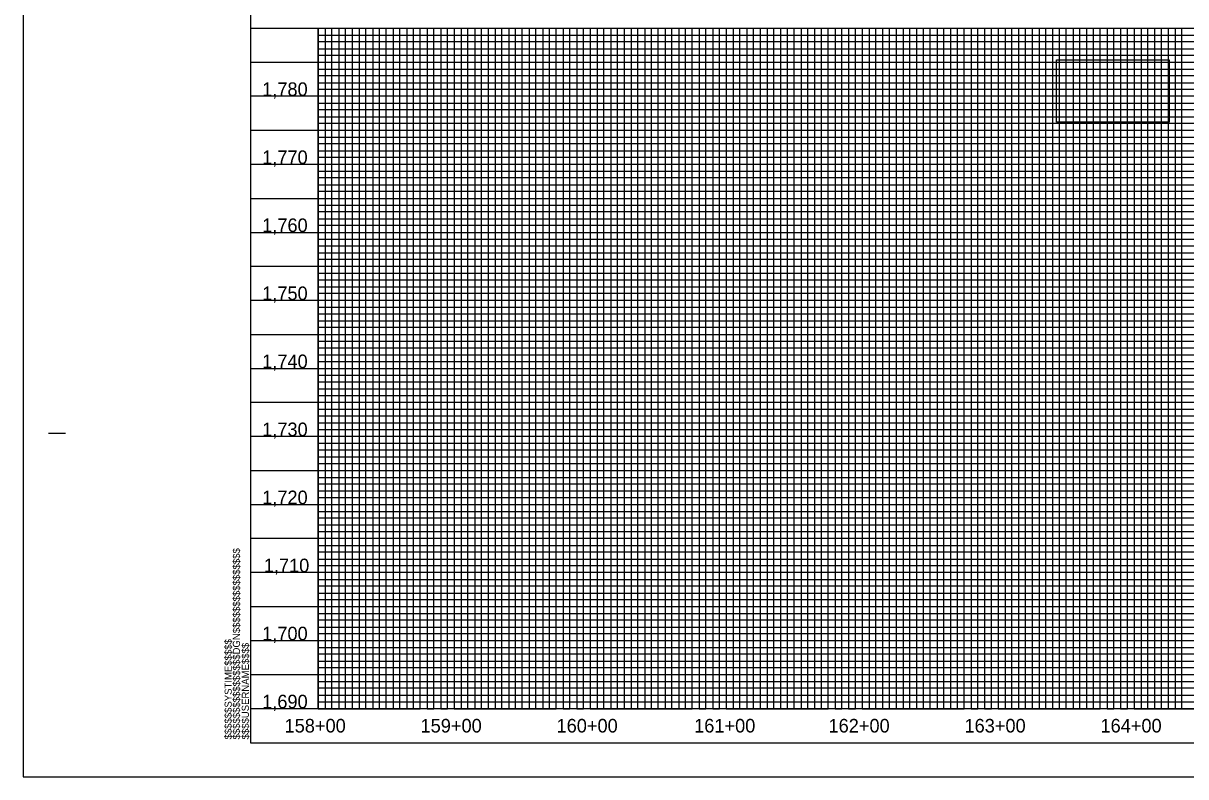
# Model space of a CAD drawing. Extents: x 505602 to 507286, y 483109 to 484209.
# Drawn here: x 505602 to 506457, y 483109 to 483662 of the extents above; entities that cross this region are included whole.
import ezdxf

# ---------------------------------------------------------------- set-up
doc = ezdxf.new("R2010")
doc.units = 0
for name, color, linetype in [('Exist Vertical Profile Vertical Axis Label', 7, 'Continuous'), ('Prop Grid Mask', 7, 'Continuous'), ('Sheet Layout Profile Border Port 2', 7, 'Continuous'), ('Sheet Plot Border Outside CELL', 7, 'Continuous'), ('Sheet Profile CELL', 7, 'Continuous'), ('Sheet Profile Grid Major CELL', 7, 'Continuous'), ('Sheet Profile Grid Middle CELL', 7, 'Continuous'), ('Sheet Profile Grid Minor CELL', 7, 'Continuous')]:
    doc.layers.add(name, color=color, linetype=linetype)

msp = doc.modelspace()

# ---------------------------------------------------------------- linework, layer by layer
at = {"layer": 'Prop Grid Mask'}
msp.add_lwpolyline([(506362.01, 483635.44), (506444.87, 483635.44), (506444.87, 483589.8), (506362.01, 483589.8)], close=True, dxfattribs=at)
at = {"layer": 'Sheet Layout Profile Border Port 2'}
msp.add_lwpolyline([(505819.08, 483658.71), (507219.08, 483658.71), (507219.08, 483158.71), (505819.08, 483158.71)], close=True, dxfattribs=at)
at = {"layer": 'Sheet Plot Border Outside CELL'}
msp.add_lwpolyline([(505602.08, 483108.71), (507286.08, 483108.71), (507286.08, 484208.71), (505602.08, 484208.71)], close=True, dxfattribs=at)
at = {"layer": 'Sheet Profile CELL'}
for p, q in [((505769.08, 483658.71), (507269.08, 483658.71)), ((505620.58, 483361.21), (505633.08, 483361.21)), ((507269.08, 483158.71), (505769.08, 483158.71)), ((505769.08, 483133.71), (507269.08, 483133.71)), ((505769.08, 483133.71), (505769.08, 483133.71)), ((505769.08, 483133.71), (505769.08, 483133.71)), ((505769.08, 483133.71), (505769.08, 483133.71)), ((505769.08, 483133.71), (505769.08, 483133.71)), ((505769.08, 483133.71), (505769.08, 483133.71)), ((505769.08, 483133.71), (505769.08, 483133.71)), ((505769.08, 483133.71), (505769.08, 483133.71))]:
    msp.add_line(p, q, dxfattribs=at)
msp.add_lwpolyline([(507269.08, 484183.71), (505769.08, 484183.71), (505769.08, 483133.71), (507269.08, 483133.71)], close=True, dxfattribs=at)
msp.add_lwpolyline([(505806.58, 483133.71), (505806.58, 483133.71)], dxfattribs=at)
at = {"layer": 'Sheet Profile Grid Major CELL'}
for p, q in [((506269.08, 483658.71), (506319.08, 483658.71)), ((506369.08, 483658.71), (506419.08, 483658.71))]:
    msp.add_line(p, q, dxfattribs=at)
for points in [[(505819.08, 483658.71), (505819.08, 483158.71), (505869.08, 483158.71), (505869.08, 483658.71), (505919.08, 483658.71), (505919.08, 483158.71), (505969.08, 483158.71), (505969.08, 483658.71), (506019.08, 483658.71), (506019.08, 483158.71), (506069.08, 483158.71), (506069.08, 483658.71), (506119.08, 483658.71), (506119.08, 483158.71), (506169.08, 483158.71), (506169.08, 483658.71), (506219.08, 483658.71), (506219.08, 483158.71), (506269.08, 483158.71), (506269.08, 483658.71), (506319.08, 483658.71), (506319.08, 483158.71), (506369.08, 483158.71), (506369.08, 483658.71), (506419.08, 483658.71), (506419.08, 483158.71), (506469.08, 483158.71)], [(507269.08, 483608.71), (505769.08, 483608.71)], [(507269.08, 483558.71), (505769.08, 483558.71), (505769.08, 483508.71), (507269.08, 483508.71)], [(507269.08, 483458.71), (505769.08, 483458.71), (505769.08, 483408.71), (507269.08, 483408.71)], [(507269.08, 483358.71), (505769.08, 483358.71), (505769.08, 483308.71), (507269.08, 483308.71)], [(507269.08, 483258.71), (505769.08, 483258.71), (505769.08, 483258.71), (505769.08, 483208.71), (507269.08, 483208.71)], [(507269.08, 483158.71), (505769.08, 483158.71)]]:
    msp.add_lwpolyline(points, dxfattribs=at)
at = {"layer": 'Sheet Profile Grid Middle CELL'}
for points in [[(505794.08, 483658.71), (505844.08, 483658.71), (505844.08, 483158.71), (505894.08, 483158.71), (505894.08, 483658.71), (505944.08, 483658.71), (505944.08, 483158.71), (505994.08, 483158.71), (505994.08, 483658.71), (506044.08, 483658.71), (506044.08, 483158.71), (506094.08, 483158.71), (506094.08, 483658.71), (506144.08, 483658.71), (506144.08, 483158.71), (506194.08, 483158.71), (506194.08, 483658.71), (506244.08, 483658.71), (506244.08, 483158.71), (506294.08, 483158.71), (506294.08, 483658.71), (506344.08, 483658.71), (506344.08, 483158.71), (506394.08, 483158.71), (506394.08, 483158.71), (506394.08, 483658.71), (506444.08, 483658.71), (506444.08, 483158.71), (506494.08, 483158.71)], [(505769.08, 483633.71), (507269.08, 483633.71)], [(507269.08, 483583.71), (505769.08, 483583.71), (505769.08, 483533.71), (507269.08, 483533.71)], [(507269.08, 483483.71), (505769.08, 483483.71), (505769.08, 483433.71), (507269.08, 483433.71)], [(507269.08, 483383.71), (505769.08, 483383.71), (505769.08, 483333.71), (507269.08, 483333.71)], [(507269.08, 483283.71), (505769.08, 483283.71), (505769.08, 483233.71), (507269.08, 483233.71)], [(507269.08, 483183.71), (505769.08, 483183.71)]]:
    msp.add_lwpolyline(points, dxfattribs=at)
at = {"layer": 'Sheet Profile Grid Minor CELL'}
for p, q in [((505819.08, 483653.71), (507219.08, 483653.71)), ((507219.08, 483648.71), (505819.08, 483648.71)), ((505819.08, 483643.71), (507219.08, 483643.71)), ((507219.08, 483638.71), (505819.08, 483638.71)), ((505819.08, 483628.71), (507219.08, 483628.71)), ((507219.08, 483623.71), (505819.08, 483623.71)), ((505819.08, 483618.71), (507219.08, 483618.71)), ((507219.08, 483613.71), (505819.08, 483613.71)), ((505819.08, 483603.71), (507219.08, 483603.71)), ((507219.08, 483598.71), (505819.08, 483598.71)), ((505819.08, 483593.71), (507219.08, 483593.71)), ((507219.08, 483588.71), (505819.08, 483588.71)), ((505819.08, 483578.71), (507219.08, 483578.71)), ((507219.08, 483573.71), (505819.08, 483573.71)), ((505819.08, 483568.71), (507219.08, 483568.71)), ((507219.08, 483563.71), (505819.08, 483563.71)), ((505819.08, 483553.71), (507219.08, 483553.71)), ((507219.08, 483548.71), (505819.08, 483548.71)), ((505819.08, 483543.71), (507219.08, 483543.71)), ((507219.08, 483538.71), (505819.08, 483538.71)), ((505819.08, 483528.71), (507219.08, 483528.71)), ((507219.08, 483523.71), (505819.08, 483523.71)), ((505819.08, 483518.71), (507219.08, 483518.71)), ((507219.08, 483513.71), (505819.08, 483513.71)), ((505819.08, 483503.71), (507219.08, 483503.71)), ((507219.08, 483498.71), (505819.08, 483498.71)), ((505819.08, 483493.71), (507219.08, 483493.71)), ((507219.08, 483488.71), (505819.08, 483488.71)), ((505819.08, 483478.71), (507219.08, 483478.71)), ((507219.08, 483473.71), (505819.08, 483473.71)), ((505819.08, 483468.71), (507219.08, 483468.71)), ((507219.08, 483463.71), (505819.08, 483463.86)), ((505819.08, 483453.71), (507219.08, 483453.71)), ((507219.08, 483448.71), (505819.08, 483448.71)), ((505819.08, 483443.71), (507219.08, 483443.71)), ((507219.08, 483438.71), (505819.08, 483438.71)), ((505819.08, 483428.71), (507219.08, 483428.71)), ((507219.08, 483423.71), (505819.08, 483423.71)), ((505819.08, 483418.71), (507219.08, 483418.71)), ((507219.08, 483413.71), (505819.08, 483413.71)), ((505819.08, 483403.71), (507219.08, 483403.71)), ((507219.08, 483398.71), (505819.08, 483398.71)), ((505819.08, 483393.71), (507219.08, 483393.71)), ((507219.08, 483388.71), (505819.08, 483388.71)), ((505819.08, 483378.71), (507219.08, 483378.71)), ((507219.08, 483373.71), (505819.08, 483373.71)), ((505819.08, 483368.71), (507219.08, 483368.71)), ((507219.08, 483363.71), (505819.08, 483363.71)), ((505819.08, 483353.71), (507219.08, 483353.71)), ((507219.08, 483348.71), (505819.08, 483348.71)), ((505819.08, 483343.71), (507219.08, 483343.71)), ((507219.08, 483338.71), (505819.08, 483338.71)), ((505819.08, 483328.71), (507219.08, 483328.71)), ((507219.08, 483323.71), (505819.08, 483323.71)), ((505819.08, 483318.71), (507219.08, 483318.71)), ((507219.08, 483313.71), (505819.08, 483313.71)), ((505819.08, 483303.71), (507219.08, 483303.71)), ((507219.08, 483298.71), (505819.08, 483298.71)), ((505819.08, 483293.71), (507219.08, 483293.71)), ((507219.08, 483288.71), (505819.08, 483288.71)), ((505819.08, 483278.71), (507219.08, 483278.71)), ((507219.08, 483273.71), (505819.08, 483273.71)), ((505819.08, 483268.71), (507219.08, 483268.71)), ((507219.08, 483263.71), (505819.08, 483263.71)), ((505819.08, 483253.71), (507219.08, 483253.71)), ((507219.08, 483248.71), (505819.08, 483248.71)), ((505819.08, 483243.71), (507219.08, 483243.71)), ((507219.08, 483238.71), (505819.08, 483238.71)), ((505819.08, 483228.71), (507219.08, 483228.71)), ((507219.08, 483223.71), (505819.08, 483223.71)), ((505819.08, 483218.71), (507219.08, 483218.71)), ((507219.08, 483213.71), (505819.08, 483213.71)), ((505819.08, 483203.71), (507219.08, 483203.71)), ((507219.08, 483198.71), (505819.08, 483198.71)), ((505819.08, 483193.71), (507219.08, 483193.71)), ((507219.08, 483188.71), (505819.08, 483188.71)), ((505819.08, 483178.71), (507219.08, 483178.71)), ((507219.08, 483173.71), (505819.08, 483173.71)), ((505819.08, 483168.71), (507219.08, 483168.71)), ((505819.08, 483163.71), (507219.08, 483163.71))]:
    msp.add_line(p, q, dxfattribs=at)
for points in [[(505819.08, 483658.71), (505824.08, 483658.71), (505824.08, 483158.71), (505829.08, 483158.71), (505829.08, 483658.71), (505834.08, 483658.71), (505834.08, 483158.71), (505839.08, 483158.71), (505839.08, 483658.71), (505849.08, 483658.71), (505849.08, 483158.71), (505854.08, 483158.71), (505854.08, 483658.71), (505859.08, 483658.71), (505859.08, 483158.71), (505864.08, 483158.71), (505874.08, 483158.71), (505879.08, 483158.71), (505879.08, 483658.71), (505884.08, 483658.71), (505884.08, 483158.71), (505889.08, 483158.71), (505889.08, 483658.71), (505899.08, 483658.71), (505899.08, 483158.71), (505904.08, 483158.71), (505904.08, 483658.71), (505909.08, 483658.71), (505909.08, 483158.71), (505914.08, 483158.71), (505914.08, 483658.71), (505924.08, 483658.71), (505924.08, 483158.71), (505929.08, 483158.71), (505929.08, 483658.71), (505934.08, 483658.71), (505934.08, 483158.71), (505939.08, 483158.71), (505939.08, 483658.71), (505949.08, 483658.71), (505949.08, 483158.71), (505954.08, 483158.71), (505954.08, 483658.71), (505959.08, 483658.71), (505959.08, 483158.71), (505964.08, 483158.71), (505964.08, 483658.71), (505974.08, 483658.71), (505974.08, 483158.71), (505979.08, 483158.71), (505979.08, 483658.71), (505984.08, 483658.71), (505984.08, 483158.71), (505989.08, 483158.71), (505989.08, 483658.71), (505999.08, 483658.71), (505999.08, 483158.71), (506004.08, 483158.71), (506004.08, 483658.71), (506009.08, 483658.71), (506009.08, 483158.71), (506014.08, 483158.71), (506014.08, 483658.71), (506024.08, 483658.71), (506024.08, 483158.71), (506029.08, 483158.71), (506029.08, 483658.71), (506034.08, 483658.71), (506034.08, 483158.71)], [(505864.08, 483158.71), (505864.08, 483658.71), (505874.08, 483658.71), (505874.08, 483158.71)], [(506034.08, 483158.71), (506039.08, 483158.71), (506039.08, 483658.71), (506049.08, 483658.71), (506049.08, 483158.71), (506054.08, 483158.71), (506054.08, 483658.71), (506059.08, 483658.71), (506059.08, 483158.71), (506064.08, 483158.71), (506064.08, 483658.71), (506074.08, 483658.71), (506074.08, 483158.71), (506079.08, 483158.71), (506079.08, 483658.71), (506084.08, 483658.71), (506084.08, 483158.71), (506089.08, 483158.71), (506089.08, 483658.71), (506099.08, 483658.71), (506099.08, 483158.71), (506104.08, 483158.71), (506104.08, 483658.71), (506109.08, 483658.71), (506109.08, 483158.71), (506114.08, 483158.71), (506114.08, 483658.71), (506124.08, 483658.71), (506124.08, 483158.71), (506129.08, 483158.71), (506129.08, 483658.71), (506134.08, 483658.71), (506134.08, 483158.71), (506139.08, 483158.71), (506139.08, 483658.71), (506149.08, 483658.71), (506149.08, 483158.71), (506154.08, 483158.71), (506154.08, 483658.71), (506159.08, 483658.71), (506159.08, 483158.71), (506164.08, 483158.71), (506164.08, 483658.71), (506174.08, 483658.71), (506174.08, 483158.71), (506179.08, 483158.71), (506179.08, 483658.71), (506184.08, 483658.71), (506184.08, 483158.71), (506189.08, 483158.71), (506189.08, 483658.71), (506199.08, 483658.71), (506199.08, 483158.71), (506204.08, 483158.71), (506204.08, 483658.71), (506209.08, 483658.71), (506209.08, 483158.71), (506214.08, 483158.71), (506214.08, 483658.71), (506224.08, 483658.71), (506224.08, 483158.71), (506229.08, 483158.71), (506229.08, 483658.71), (506234.08, 483658.71), (506234.08, 483158.71), (506239.08, 483158.71), (506239.08, 483658.71), (506249.08, 483658.71), (506249.08, 483158.71), (506254.08, 483158.71), (506254.08, 483658.71), (506259.08, 483658.71), (506259.08, 483158.71), (506264.08, 483158.71), (506264.08, 483658.71), (506274.08, 483658.71), (506274.08, 483158.71), (506279.08, 483158.71), (506279.08, 483658.71), (506284.08, 483658.71), (506284.08, 483158.71), (506289.08, 483158.71), (506289.08, 483658.71), (506299.08, 483658.71), (506299.08, 483158.71), (506304.08, 483158.71), (506304.08, 483658.71), (506309.08, 483658.71), (506309.08, 483158.71), (506314.08, 483158.71), (506314.08, 483658.71), (506324.08, 483658.71), (506324.08, 483158.71), (506329.08, 483158.71), (506329.08, 483658.71), (506334.08, 483658.71), (506334.08, 483158.71), (506339.08, 483158.71), (506339.08, 483658.71), (506349.08, 483658.71)], [(506349.08, 483658.71), (506349.08, 483158.71), (506354.08, 483158.71), (506354.08, 483658.71), (506359.08, 483658.71), (506359.08, 483158.71), (506364.08, 483158.71), (506364.08, 483658.71), (506374.08, 483658.71), (506374.08, 483158.71), (506379.08, 483158.71), (506379.08, 483658.71), (506384.08, 483658.71), (506384.08, 483158.71), (506389.08, 483158.71), (506389.08, 483658.71), (506399.08, 483658.71), (506399.08, 483158.71), (506404.08, 483158.71), (506404.08, 483658.71), (506409.08, 483658.71), (506409.08, 483158.71), (506414.08, 483158.71), (506414.08, 483658.71), (506424.08, 483658.71), (506424.08, 483158.71), (506429.08, 483158.71), (506429.08, 483658.71), (506434.08, 483658.71), (506434.08, 483158.71), (506439.08, 483158.71), (506439.08, 483658.71), (506449.08, 483658.71), (506449.08, 483158.71), (506454.08, 483158.71), (506454.08, 483658.71), (506459.08, 483658.71)]]:
    msp.add_lwpolyline(points, dxfattribs=at)

# ---------------------------------------------------------------- texts
at = {"layer": 'Exist Vertical Profile Vertical Axis Label'}
for s, p in [('1,780', (505777.78, 483608.96)), ('1,770', (505777.78, 483558.96)), ('1,760', (505777.78, 483508.96)), ('1,750', (505777.78, 483458.96)), ('1,740', (505777.78, 483408.96)), ('1,730', (505777.78, 483358.96)), ('1,720', (505777.78, 483308.96)), ('1,710', (505778.97, 483258.96)), ('1,700', (505777.78, 483208.96)), ('1,690', (505777.78, 483158.96)), ('158+00', (505794.26, 483141.21)), ('159+00', (505894.26, 483141.21)), ('160+00', (505994.26, 483141.21)), ('161+00', (506095.45, 483141.21)), ('162+00', (506194.26, 483141.21)), ('163+00', (506294.26, 483141.21)), ('164+00', (506394.26, 483141.21))]:
    msp.add_text(s, height=10, dxfattribs=at).set_placement(p)
at = {"layer": 'Sheet Profile CELL'}
for s, p in [('$$$$$$$$$$$$$$$$DGN$$$$$$$$$$$$$$$$', (505761.44, 483136.09)), ('$$$$$$SYSTIME$$$$$', (505755.39, 483136.09)), ('$$$$USERNAME$$$$', (505768.02, 483136.1))]:
    msp.add_text(s, height=5.25, rotation=90, dxfattribs=at).set_placement(p)

doc.saveas('drawing.dxf')
